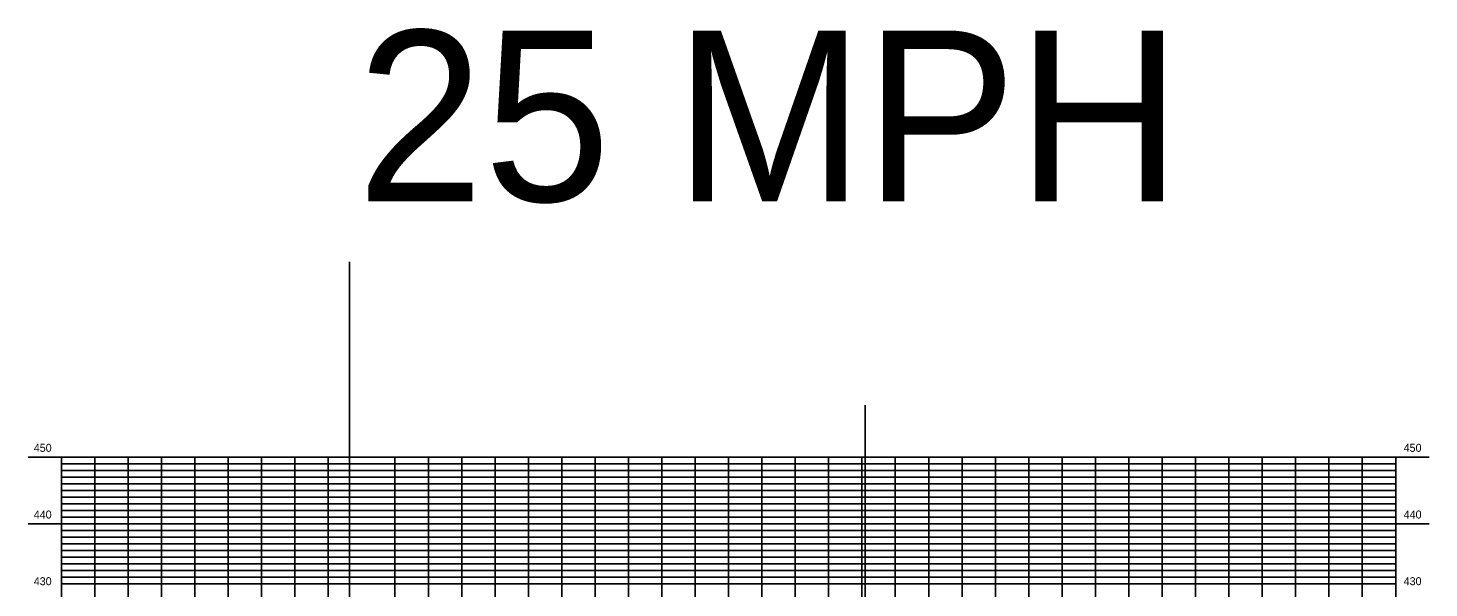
# Model space of a CAD drawing. Extents: x 1195880 to 1289360, y 2059330 to 2086925.
# Drawn here: x 1203089 to 1204139, y 2065566 to 2065986 of the extents above; entities that cross this region are included whole.
import ezdxf

# ---------------------------------------------------------------- set-up
doc = ezdxf.new("R2010")
doc.units = 0
for name, color, linetype in [('Default', 7, 'Continuous'), ('Grid', 7, 'Continuous'), ('Grid Lables', 7, 'Continuous')]:
    doc.layers.add(name, color=color, linetype=linetype)

msp = doc.modelspace()

# ---------------------------------------------------------------- linework, layer by layer
at = {"layer": 'Default'}
for p, q in [((1203330.3, 2064864.2), (1203330.3, 2065810.6)), ((1203716.9, 2064864.2), (1203716.9, 2065703.2))]:
    msp.add_line(p, q, dxfattribs=at)
at = {"layer": 'Grid'}
for p, q in [((1203089.4, 2065664.2), (1203114.4, 2065664.2)), ((1203089.4, 2065664.2), (1203114.4, 2065664.2)), ((1203114.4, 2064864.2), (1203114.4, 2065664.2)), ((1203114.4, 2065664.2), (1204114.4, 2065664.2)), ((1203114.4, 2065664.2), (1204114.4, 2065664.2)), ((1203114.4, 2065659.2), (1203117.4, 2065659.2)), ((1203114.4, 2065659.2), (1204114.4, 2065659.2)), ((1203139.4, 2064864.2), (1203139.4, 2065664.2)), ((1203164.4, 2064864.2), (1203164.4, 2065664.2)), ((1203189.4, 2064864.2), (1203189.4, 2065664.2)), ((1203214.4, 2064864.2), (1203214.4, 2065664.2)), ((1203239.4, 2064864.2), (1203239.4, 2065664.2)), ((1203264.4, 2064864.2), (1203264.4, 2065664.2)), ((1203289.4, 2064864.2), (1203289.4, 2065664.2)), ((1203314.4, 2064864.2), (1203314.4, 2065664.2)), ((1203364.4, 2064864.2), (1203364.4, 2065664.2)), ((1203389.4, 2064864.2), (1203389.4, 2065664.2)), ((1203414.4, 2064864.2), (1203414.4, 2065664.2)), ((1203439.4, 2064864.2), (1203439.4, 2065664.2)), ((1203464.4, 2064864.2), (1203464.4, 2065664.2)), ((1203489.4, 2064864.2), (1203489.4, 2065664.2)), ((1203514.4, 2064864.2), (1203514.4, 2065664.2)), ((1203539.4, 2064864.2), (1203539.4, 2065664.2)), ((1203564.4, 2064864.2), (1203564.4, 2065664.2)), ((1203589.4, 2064864.2), (1203589.4, 2065664.2)), ((1203614.4, 2064864.2), (1203614.4, 2065664.2)), ((1203639.4, 2064864.2), (1203639.4, 2065664.2)), ((1203664.4, 2064864.2), (1203664.4, 2065664.2)), ((1203689.4, 2064864.2), (1203689.4, 2065664.2)), ((1203714.4, 2064864.2), (1203714.4, 2065664.2)), ((1203739.4, 2064864.2), (1203739.4, 2065664.2)), ((1203764.4, 2064864.2), (1203764.4, 2065664.2)), ((1203789.4, 2064864.2), (1203789.4, 2065664.2)), ((1203814.4, 2064864.2), (1203814.4, 2065664.2)), ((1203839.4, 2064864.2), (1203839.4, 2065664.2)), ((1203864.4, 2064864.2), (1203864.4, 2065664.2)), ((1203889.4, 2064864.2), (1203889.4, 2065664.2)), ((1203914.4, 2064864.2), (1203914.4, 2065664.2)), ((1203939.4, 2064864.2), (1203939.4, 2065664.2)), ((1203964.4, 2064864.2), (1203964.4, 2065664.2)), ((1203989.4, 2064864.2), (1203989.4, 2065664.2)), ((1204014.4, 2064864.2), (1204014.4, 2065664.2)), ((1204039.4, 2064864.2), (1204039.4, 2065664.2)), ((1204064.4, 2064864.2), (1204064.4, 2065664.2)), ((1204089.4, 2064864.2), (1204089.4, 2065664.2)), ((1204114.4, 2064864.2), (1204114.4, 2065664.2)), ((1204139.4, 2065664.2), (1204114.4, 2065664.2)), ((1204139.4, 2065664.2), (1204114.4, 2065664.2)), ((1203114.4, 2065654.2), (1203117.4, 2065654.2)), ((1203114.4, 2065654.2), (1204114.4, 2065654.2)), ((1204114.4, 2065654.2), (1203114.4, 2065654.2)), ((1203114.4, 2065649.2), (1203117.4, 2065649.2)), ((1203114.4, 2065649.2), (1204114.4, 2065649.2)), ((1203114.4, 2065644.2), (1203117.4, 2065644.2)), ((1203114.4, 2065644.2), (1204114.4, 2065644.2)), ((1204114.4, 2065644.2), (1203114.4, 2065644.2)), ((1203114.4, 2065639.2), (1203117.4, 2065639.2)), ((1203114.4, 2065639.2), (1204114.4, 2065639.2)), ((1203114.4, 2065634.2), (1203117.4, 2065634.2)), ((1203114.4, 2065634.2), (1204114.4, 2065634.2)), ((1204114.4, 2065634.2), (1203114.4, 2065634.2)), ((1203114.4, 2065629.2), (1203117.4, 2065629.2)), ((1203114.4, 2065629.2), (1204114.4, 2065629.2)), ((1203114.4, 2065624.2), (1203117.4, 2065624.2)), ((1203114.4, 2065624.2), (1204114.4, 2065624.2)), ((1204114.4, 2065624.2), (1203114.4, 2065624.2)), ((1203089.4, 2065614.2), (1203114.4, 2065614.2)), ((1203114.4, 2065619.2), (1203117.4, 2065619.2)), ((1203114.4, 2065619.2), (1204114.4, 2065619.2)), ((1203114.4, 2065614.2), (1204114.4, 2065614.2)), ((1204139.4, 2065614.2), (1204114.4, 2065614.2)), ((1203114.4, 2065609.2), (1203117.4, 2065609.2)), ((1203114.4, 2065609.2), (1204114.4, 2065609.2)), ((1203114.4, 2065604.2), (1203117.4, 2065604.2)), ((1203114.4, 2065604.2), (1204114.4, 2065604.2)), ((1204114.4, 2065604.2), (1203114.4, 2065604.2)), ((1203114.4, 2065599.2), (1203117.4, 2065599.2)), ((1203114.4, 2065599.2), (1204114.4, 2065599.2)), ((1203114.4, 2065594.2), (1203117.4, 2065594.2)), ((1203114.4, 2065594.2), (1204114.4, 2065594.2)), ((1204114.4, 2065594.2), (1203114.4, 2065594.2)), ((1203114.4, 2065589.2), (1203117.4, 2065589.2)), ((1203114.4, 2065589.2), (1204114.4, 2065589.2)), ((1203114.4, 2065584.2), (1203117.4, 2065584.2)), ((1203114.4, 2065584.2), (1204114.4, 2065584.2)), ((1204114.4, 2065584.2), (1203114.4, 2065584.2)), ((1203114.4, 2065579.2), (1203117.4, 2065579.2)), ((1203114.4, 2065579.2), (1204114.4, 2065579.2)), ((1203114.4, 2065574.2), (1203117.4, 2065574.2)), ((1203114.4, 2065574.2), (1204114.4, 2065574.2)), ((1204114.4, 2065574.2), (1203114.4, 2065574.2)), ((1203114.4, 2065569.2), (1203117.4, 2065569.2)), ((1203114.4, 2065569.2), (1204114.4, 2065569.2))]:
    msp.add_line(p, q, dxfattribs=at)

# ---------------------------------------------------------------- texts
at = {"layer": 'Default'}
msp.add_text('25 MPH', height=128, rotation=360, dxfattribs=at).set_placement((1203335.7, 2065856))
at = {"layer": 'Grid Lables'}
for s, p in [('450', (1203093.7, 2065668.2)), ('450', (1203093.7, 2065668.2)), ('450', (1204120.4, 2065668.2)), ('450', (1204120.4, 2065668.2)), ('440', (1203093.7, 2065618.2)), ('440', (1204120.4, 2065618.2)), ('430', (1203093.7, 2065568.2)), ('430', (1204120.4, 2065568.2))]:
    msp.add_text(s, height=6, dxfattribs=at).set_placement(p)

doc.saveas('drawing.dxf')
